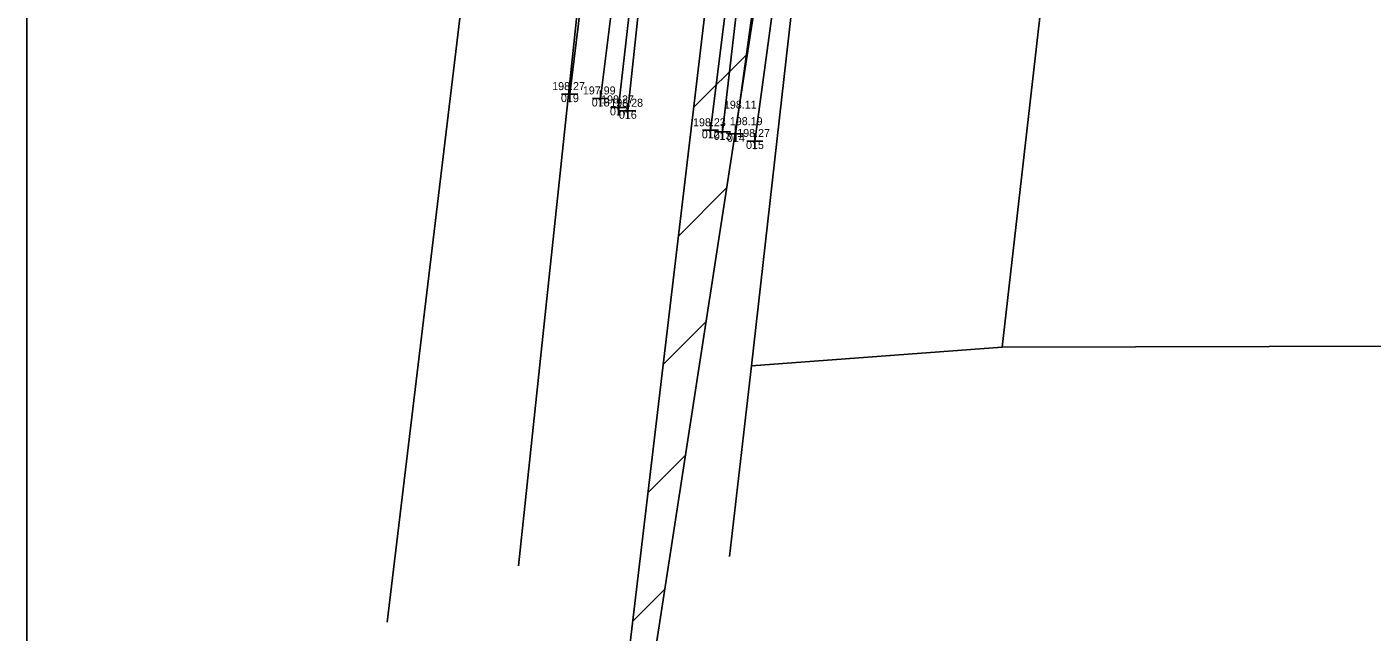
# Model space of a CAD drawing. Extents: x -706655 to -706193, y -1036183 to -1034979.
# Drawn here: x -706654.8 to -706570.7, y -1035178.8 to -1035141 of the extents above; entities that cross this region are included whole.
import ezdxf

# ---------------------------------------------------------------- set-up
doc = ezdxf.new("R2010")
doc.units = 0
for name, color, linetype in [('CETIN', 7, 'Continuous'), ('Hranice parcel', 7, 'Continuous'), ('křížky', 7, 'Continuous'), ('Nová vrstva (4)', 7, 'Continuous'), ('Stávající terén', 7, 'Continuous'), ('Vrstva 54', 7, 'Continuous'), ('výšky', 7, 'Continuous'), ('čísla bodu', 7, 'Continuous')]:
    doc.layers.add(name, color=color, linetype=linetype)

msp = doc.modelspace()

# ---------------------------------------------------------------- linework, layer by layer
at = {"layer": 'CETIN'}
msp.add_lwpolyline([(-706632.29, -1035178.176), (-706624.38, -1035112.55), (-706623.72, -1035104.98), (-706623.414, -1035102.598), (-706615.872, -1035043.919)], dxfattribs=at)
at = {"layer": 'Hranice parcel'}
for p, q in [((-706617.66, -1035114.1), (-706620.85, -1035144.24)), ((-706604.25, -1035115.63), (-706609.53, -1035162.16)), ((-706593.85, -1035161), (-706588.9, -1035117.59)), ((-706624.07, -1035174.66), (-706620.85, -1035144.24)), ((-706593.85, -1035161), (-706609.53, -1035162.16)), ((-706470.57, -1035160.7), (-706593.85, -1035161)), ((-706609.53, -1035162.16), (-706610.888, -1035174.077))]:
    msp.add_line(p, q, dxfattribs=at)
at = {"layer": 'křížky'}
for p, q in [((-706620.88, -1035145.69), (-706620.88, -1035144.69)), ((-706618.96, -1035145.96), (-706618.96, -1035144.96)), ((-706621.38, -1035145.19), (-706620.38, -1035145.19)), ((-706620.88, -1035145.19), (-706620.88, -1035145.19)), ((-706619.46, -1035145.46), (-706618.46, -1035145.46)), ((-706618.96, -1035145.46), (-706618.96, -1035145.46)), ((-706617.82, -1035146.52), (-706617.82, -1035145.52)), ((-706617.25, -1035146.73), (-706617.25, -1035145.73)), ((-706618.32, -1035146.02), (-706617.32, -1035146.02)), ((-706617.82, -1035146.02), (-706617.82, -1035146.02)), ((-706617.75, -1035146.23), (-706616.75, -1035146.23)), ((-706617.25, -1035146.23), (-706617.25, -1035146.23)), ((-706612.58, -1035147.45), (-706611.58, -1035147.45)), ((-706612.08, -1035147.95), (-706612.08, -1035146.95)), ((-706612.08, -1035147.45), (-706612.08, -1035147.45)), ((-706611.84, -1035147.55), (-706610.84, -1035147.55)), ((-706611.34, -1035148.05), (-706611.34, -1035147.05)), ((-706611.34, -1035147.55), (-706611.34, -1035147.55)), ((-706610.51, -1035148.17), (-706610.51, -1035147.17)), ((-706611.01, -1035147.67), (-706610.01, -1035147.67)), ((-706610.51, -1035147.67), (-706610.51, -1035147.67)), ((-706609.82, -1035148.12), (-706608.82, -1035148.12)), ((-706609.32, -1035148.62), (-706609.32, -1035147.62)), ((-706609.32, -1035148.12), (-706609.32, -1035148.12))]:
    msp.add_line(p, q, dxfattribs=at)
at = {"layer": 'Nová vrstva (4)'}
for p, q in [((-706608.43, -1035106.29), (-706622.552, -1035225.456)), ((-706604.229, -1035106.738), (-706622.552, -1035225.456)), ((-706613.14, -1035146.036), (-706609.775, -1035142.67)), ((-706614.091, -1035154.057), (-706611.065, -1035151.032)), ((-706615.042, -1035162.079), (-706612.356, -1035159.394)), ((-706615.992, -1035170.101), (-706613.647, -1035167.755)), ((-706616.943, -1035178.123), (-706614.937, -1035176.117))]:
    msp.add_line(p, q, dxfattribs=at)
at = {"layer": 'Stávající terén'}
for points in [[(-706608.917, -1035075.29), (-706610.31, -1035086.81), (-706611.88, -1035099.66), (-706615.39, -1035128.84), (-706617.25, -1035146.23)], [(-706612.08, -1035147.45), (-706609.84, -1035129.45), (-706609.56, -1035126.63), (-706608.3, -1035116.88), (-706606.85, -1035102.94), (-706605.26, -1035087.23), (-706604.17, -1035076.55)], [(-706630.18, -1035109.2), (-706620.44, -1035112.49), (-706618.86, -1035128.69), (-706620.88, -1035145.19)], [(-706620.44, -1035112.49), (-706616.88, -1035128.78), (-706618.96, -1035145.46)], [(-706620.44, -1035112.49), (-706616.05, -1035116.18), (-706615.87, -1035128.82), (-706617.82, -1035146.02)], [(-706611.34, -1035147.55), (-706609.22, -1035129.42), (-706605.99, -1035116.17), (-706603.37, -1035114.97)], [(-706610.51, -1035147.67), (-706607.99, -1035129.41), (-706603.37, -1035114.97)], [(-706609.32, -1035148.12), (-706606.8, -1035129.58), (-706603.37, -1035114.97)]]:
    msp.add_lwpolyline(points, dxfattribs=at)
at = {"layer": 'Vrstva 54'}
msp.add_lwpolyline([(-706654.789, -1034978.85), (-706476.789, -1034978.85), (-706476.789, -1035234.85), (-706654.789, -1035234.85)], close=True, dxfattribs=at)
at = {"layer": 'čísla bodu'}
for p, q in [((-706620.88, -1035145.69), (-706620.88, -1035144.69)), ((-706618.96, -1035145.96), (-706618.96, -1035144.96)), ((-706621.38, -1035145.19), (-706620.38, -1035145.19)), ((-706620.88, -1035145.19), (-706620.88, -1035145.19)), ((-706619.46, -1035145.46), (-706618.46, -1035145.46)), ((-706618.96, -1035145.46), (-706618.96, -1035145.46)), ((-706617.82, -1035146.52), (-706617.82, -1035145.52)), ((-706617.25, -1035146.73), (-706617.25, -1035145.73)), ((-706618.32, -1035146.02), (-706617.32, -1035146.02)), ((-706617.82, -1035146.02), (-706617.82, -1035146.02)), ((-706617.75, -1035146.23), (-706616.75, -1035146.23)), ((-706617.25, -1035146.23), (-706617.25, -1035146.23)), ((-706612.58, -1035147.45), (-706611.58, -1035147.45)), ((-706612.08, -1035147.95), (-706612.08, -1035146.95)), ((-706612.08, -1035147.45), (-706612.08, -1035147.45)), ((-706611.84, -1035147.55), (-706610.84, -1035147.55)), ((-706611.34, -1035148.05), (-706611.34, -1035147.05)), ((-706611.34, -1035147.55), (-706611.34, -1035147.55)), ((-706610.51, -1035148.17), (-706610.51, -1035147.17)), ((-706611.01, -1035147.67), (-706610.01, -1035147.67)), ((-706610.51, -1035147.67), (-706610.51, -1035147.67)), ((-706609.82, -1035148.12), (-706608.82, -1035148.12)), ((-706609.32, -1035148.62), (-706609.32, -1035147.62)), ((-706609.32, -1035148.12), (-706609.32, -1035148.12))]:
    msp.add_line(p, q, dxfattribs=at)

# ---------------------------------------------------------------- texts
at = {"layer": 'výšky'}
for s, p in [('198.27', (-706621.972, -1035144.94)), ('197.99', (-706620.056, -1035145.21)), ('198.27', (-706618.912, -1035145.77)), ('198.28', (-706618.342, -1035145.98)), ('198.11', (-706611.242, -1035146.1)), ('198.23', (-706613.172, -1035147.2)), ('198.19', (-706610.874, -1035147.13)), ('198.27', (-706610.412, -1035147.87))]:
    msp.add_text(s, height=0.5, dxfattribs=at).set_placement(p)
at = {"layer": 'čísla bodu'}
for s, p in [('019', (-706621.423, -1035145.69)), ('018', (-706619.501, -1035145.96)), ('017', (-706618.361, -1035146.52)), ('016', (-706617.805, -1035146.73)), ('012', (-706612.621, -1035147.95)), ('013', (-706611.881, -1035148.05)), ('014', (-706611.051, -1035148.17)), ('015', (-706609.861, -1035148.62))]:
    msp.add_text(s, height=0.5, dxfattribs=at).set_placement(p)

doc.saveas('drawing.dxf')
